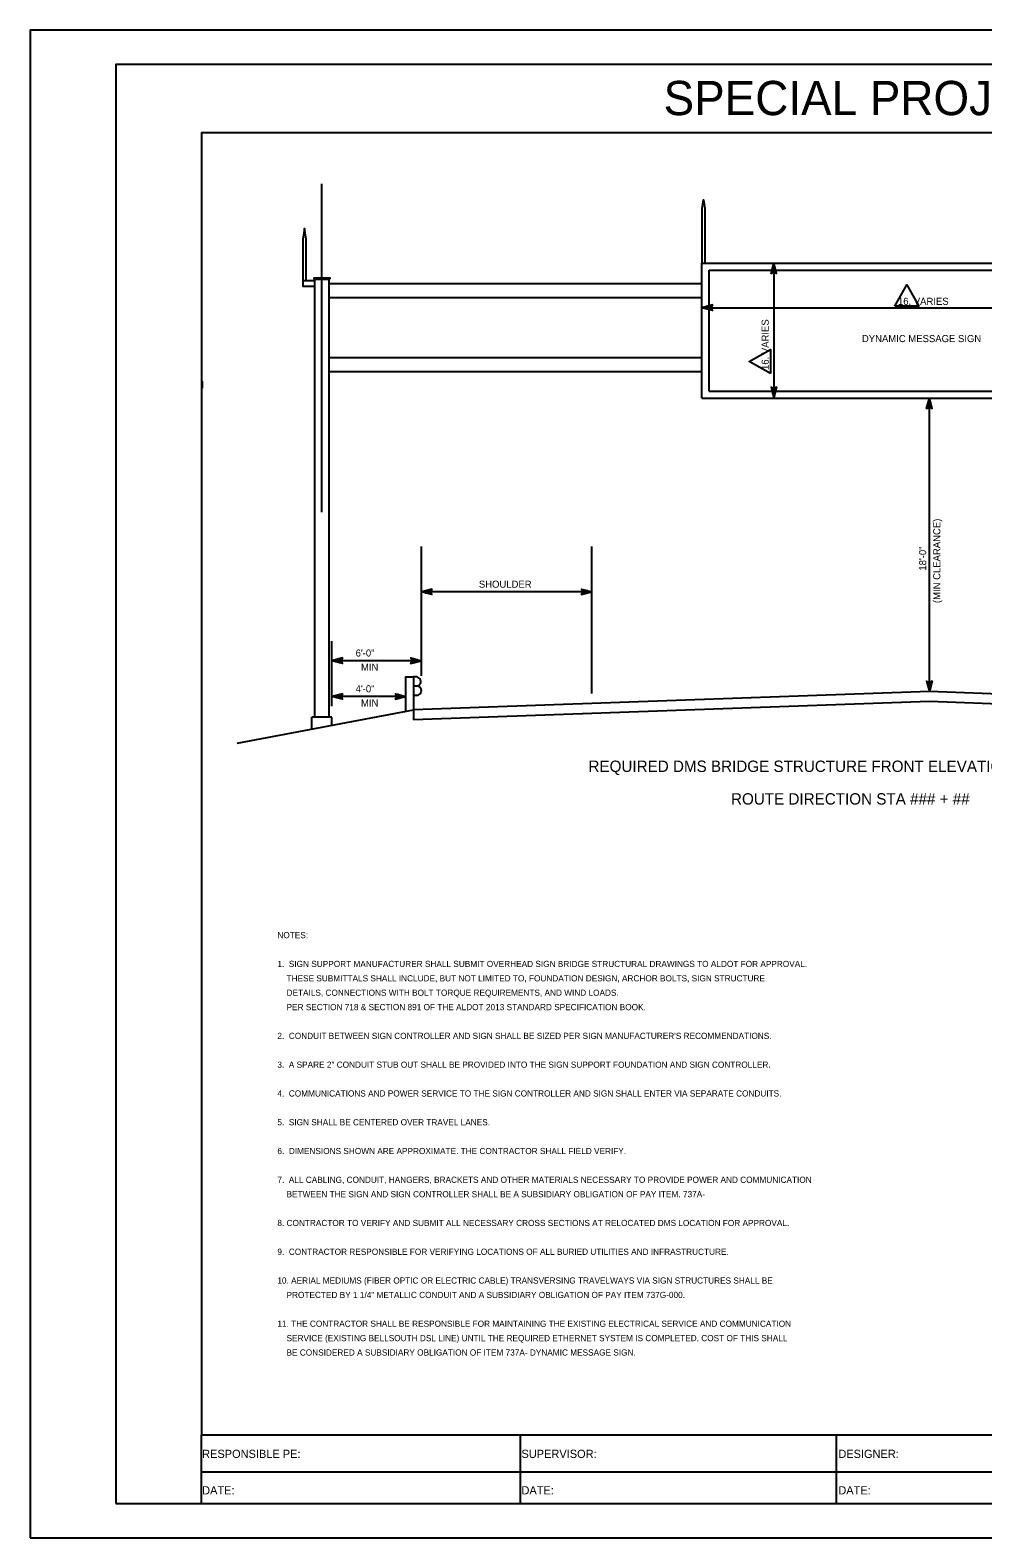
# Model space of a CAD drawing. Extents: x 515543 to 517243, y 661761 to 662861.
# Drawn here: x 515543 to 516238, y 661761 to 662861 of the extents above; entities that cross this region are included whole.
import ezdxf

# ---------------------------------------------------------------- set-up
doc = ezdxf.new("R2010")
doc.units = 0
for name, color, linetype in [('2', 7, 'Continuous'), ('ANNO-SHT', 7, 'Continuous'), ('ANNO-TXT', 7, 'Continuous'), ('AXIS', 7, 'Continuous'), ('Level 40', 7, 'Continuous'), ('Level 62', 7, 'Continuous'), ('Level 8', 7, 'Continuous'), ('LTT', 7, 'Continuous'), ('SHT-BDR', 7, 'Continuous'), ('SHT-BNDRY', 7, 'Continuous')]:
    doc.layers.add(name, color=color, linetype=linetype)

msp = doc.modelspace()

# ---------------------------------------------------------------- linework, layer by layer
at = {"layer": '2'}
msp.add_lwpolyline([(515668.1, 662604.6), (515668, 662599.6)], dxfattribs=at)
msp.add_lwpolyline([(515668.1, 662604.6), (515668, 662599.6)], dxfattribs=at)
at = {"layer": 'AXIS'}
msp.add_line((515667.5, 662385.7), (515667.5, 662385.8), dxfattribs=at)
at = {"layer": 'Level 40'}
for points in [[(516032.9, 662690.7), (516032.9, 662730.5), (516033.9, 662737), (516034.9, 662730.5), (516034.9, 662690.7)], [(515743.8, 662677.9), (515743.8, 662708.2), (515742.6, 662715.9), (515741.4, 662708.2), (515741.4, 662677.9)]]:
    msp.add_lwpolyline(points, dxfattribs=at)
msp.add_lwpolyline([(515750.2, 662677.9), (515741.4, 662677.9), (515741.4, 662674), (515750.2, 662674)], close=True, dxfattribs=at)
at = {"layer": 'Level 62'}
msp.add_lwpolyline([(515542.5, 661760.7), (517242.5, 661760.7), (517242.5, 662860.7), (515542.5, 662860.7)], close=True, dxfattribs=at)
at = {"layer": 'Level 8'}
for p, q in [((515755.4, 662509), (515755.4, 662748.7)), ((516032.7, 662592.2), (516032.7, 662690.7)), ((516037.9, 662597.4), (516037.9, 662685.6)), ((516085.1, 662690.7), (516085.1, 662592.2)), ((515749.7, 662679.1), (515761.1, 662679.1)), ((515750.2, 662359.5), (515750.2, 662679.1)), ((515760.6, 662359.5), (515760.6, 662679.1)), ((515760.6, 662676), (516032.7, 662676)), ((515760.6, 662665.6), (516032.7, 662665.6)), ((516032.7, 662658.2), (516369.7, 662658.2)), ((515760.6, 662622), (516032.7, 662622)), ((515760.6, 662611.6), (516032.7, 662611.6)), ((516037.9, 662597.4), (516364.5, 662597.4)), ((516032.7, 662592.2), (516369.7, 662592.2)), ((516198.6, 662378.1), (516198.6, 662592.2)), ((515828, 662389.6), (515828, 662484.1)), ((515952.4, 662376.7), (515952.4, 662484.1)), ((515952.4, 662450.9), (515828, 662450.9)), ((515828, 662400.7), (515762.7, 662400.7)), ((515824.1, 662388.9), (515822.3, 662389)), ((515824.4, 662382.1), (515822.3, 662382.1)), ((515816.6, 662374.6), (515762.7, 662374.6)), ((515824.8, 662375.4), (515822.3, 662375.4)), ((515748.1, 662350.8), (515748.1, 662359.5)), ((515762.7, 662359.5), (515748.1, 662359.5)), ((515762.7, 662353.6), (515762.7, 662359.5))]:
    msp.add_line(p, q, dxfattribs=at)
for points in [[(516032.7, 662690.7), (516369.7, 662690.7), (516369.7, 662592.2)], [(516037.9, 662685.6), (516364.5, 662685.6), (516364.5, 662597.4)], [(515749.7, 662679.1), (515749.7, 662680.1), (515761.1, 662680.1), (515761.1, 662679.1)], [(515816.6, 662363.7), (515816.6, 662389), (515822.3, 662389), (515822.3, 662364.8)]]:
    msp.add_lwpolyline(points, dxfattribs=at)
for centre in [(515824.2, 662385.5), (515824.6, 662378.8)]:
    msp.add_arc(centre, 3.38, 272.7797, 93.0419, dxfattribs=at)
at = {"layer": 'LTT'}
for points in [[(516083.1, 662683.1), (516085.1, 662690.7)], [(516085.1, 662684.5), (516084.4, 662687.9), (516084.4, 662684), (516083.8, 662685.3), (516083.8, 662684), (516083.1, 662683.1), (516085.1, 662684.3)], [(516087.1, 662683.1), (516085.1, 662690.7)], [(516085.1, 662684.5), (516085.8, 662687.9), (516085.8, 662684), (516086.4, 662685.3), (516086.4, 662684), (516087.1, 662683.1), (516085.1, 662684.3)], [(516040.4, 662660.2), (516032.7, 662658.2)], [(516040.4, 662656.3), (516032.7, 662658.2)], [(516039, 662658.2), (516035.6, 662658.9), (516039.5, 662658.9), (516038.2, 662659.5), (516039.5, 662659.5), (516040.4, 662660.2), (516039.2, 662658.2)], [(516039, 662658.2), (516035.6, 662657.6), (516039.5, 662657.6), (516038.2, 662656.9), (516039.5, 662656.9), (516040.4, 662656.3), (516039.2, 662658.2)], [(516085.1, 662599), (516084.4, 662595.5), (516084.4, 662599.4), (516083.8, 662598.2), (516083.8, 662599.5), (516083.1, 662600.3), (516085.1, 662599.1)], [(516083.1, 662600.3), (516085.1, 662592.7)], [(516085.1, 662599), (516085.8, 662595.5), (516085.8, 662599.4), (516086.4, 662598.2), (516086.4, 662599.5), (516087.1, 662600.3), (516085.1, 662599.1)], [(516087.1, 662600.3), (516085.1, 662592.7)], [(516196.6, 662584.6), (516198.6, 662592.2)], [(516198.6, 662586), (516197.9, 662589.4), (516197.9, 662585.5), (516197.3, 662586.8), (516197.3, 662585.5), (516196.6, 662584.6), (516198.6, 662585.8)], [(516200.6, 662584.6), (516198.6, 662592.2)], [(516198.6, 662586), (516199.3, 662589.4), (516199.3, 662585.5), (516199.9, 662586.8), (516199.9, 662585.5), (516200.6, 662584.6), (516198.6, 662585.8)], [(515835.6, 662452.9), (515828, 662450.9)], [(515835.6, 662448.9), (515828, 662450.9)], [(515834.3, 662450.9), (515830.8, 662451.6), (515834.7, 662451.6), (515833.4, 662452.2), (515834.8, 662452.2), (515835.6, 662452.9), (515834.4, 662450.9)], [(515834.3, 662450.9), (515830.8, 662450.2), (515834.7, 662450.2), (515833.4, 662449.6), (515834.8, 662449.6), (515835.6, 662448.9), (515834.4, 662450.9)], [(515946.1, 662450.9), (515949.5, 662451.6), (515945.7, 662451.6), (515946.9, 662452.2), (515945.6, 662452.2), (515944.7, 662452.9), (515946, 662450.9)], [(515944.7, 662452.9), (515952.4, 662450.9)], [(515946.1, 662450.9), (515949.5, 662450.2), (515945.7, 662450.2), (515946.9, 662449.6), (515945.6, 662449.6), (515944.7, 662448.9), (515946, 662450.9)], [(515944.7, 662448.9), (515952.4, 662450.9)], [(515770.3, 662402.7), (515762.7, 662400.7)], [(515770.3, 662398.7), (515762.7, 662400.7)], [(515768.9, 662400.7), (515765.5, 662401.4), (515769.4, 662401.4), (515768.1, 662402), (515769.4, 662402), (515770.3, 662402.7), (515769.1, 662400.7)], [(515768.9, 662400.7), (515765.5, 662400), (515769.4, 662400), (515768.1, 662399.4), (515769.4, 662399.4), (515770.3, 662398.7), (515769.1, 662400.7)], [(515821.7, 662400.7), (515825.1, 662401.4), (515821.3, 662401.4), (515822.5, 662402), (515821.2, 662402), (515820.3, 662402.7), (515821.6, 662400.7)], [(515820.3, 662402.7), (515828, 662400.7)], [(515821.7, 662400.7), (515825.1, 662400), (515821.3, 662400), (515822.5, 662399.4), (515821.2, 662399.4), (515820.3, 662398.7), (515821.6, 662400.7)], [(515820.3, 662398.7), (515828, 662400.7)], [(516198.6, 662384.4), (516197.9, 662381), (516197.9, 662384.9), (516197.3, 662383.6), (516197.3, 662384.9), (516196.6, 662385.8), (516198.6, 662384.5)], [(516196.6, 662385.8), (516198.6, 662378.1)], [(516198.6, 662384.4), (516199.3, 662381), (516199.3, 662384.9), (516199.9, 662383.6), (516199.9, 662384.9), (516200.6, 662385.8), (516198.6, 662384.5)], [(516200.6, 662385.8), (516198.6, 662378.1)], [(515770.3, 662376.6), (515762.7, 662374.6)], [(515770.3, 662372.6), (515762.7, 662374.6)], [(515768.9, 662374.6), (515765.5, 662375.3), (515769.4, 662375.3), (515768.1, 662375.9), (515769.4, 662375.9), (515770.3, 662376.6), (515769.1, 662374.6)], [(515768.9, 662374.6), (515765.5, 662373.9), (515769.4, 662373.9), (515768.1, 662373.3), (515769.4, 662373.3), (515770.3, 662372.6), (515769.1, 662374.6)], [(515810.4, 662374.6), (515813.8, 662375.3), (515809.9, 662375.3), (515811.2, 662375.9), (515809.9, 662375.9), (515809, 662376.6), (515810.2, 662374.6)], [(515809, 662376.6), (515816.6, 662374.6)], [(515810.4, 662374.6), (515813.8, 662373.9), (515809.9, 662373.9), (515811.2, 662373.3), (515809.9, 662373.3), (515809, 662372.6), (515810.2, 662374.6)], [(515809, 662372.6), (515816.6, 662374.6)]]:
    msp.add_lwpolyline(points, dxfattribs=at)
at = {"layer": 'SHT-BDR'}
msp.add_lwpolyline([(515667.5, 661835.8), (517167.5, 661835.8), (517167.5, 662785.8), (515667.5, 662785.8)], close=True, dxfattribs=at)
at = {"layer": 'SHT-BNDRY'}
for p, q in [((515762.7, 662367.5), (515762.7, 662415)), ((516198.6, 662378.1), (515822.3, 662364.8)), ((516580.1, 662364.8), (516198.6, 662378.1)), ((516198.6, 662370.8), (515822.3, 662357.5)), ((516580.1, 662357.5), (516198.6, 662370.8)), ((515693.6, 662340.6), (515822.3, 662364.8)), ((515822.3, 662364.8), (515822.3, 662357.5)), ((515667.5, 661785.7), (515667.5, 661835.8)), ((515900.1, 661835.8), (515900.1, 661785.7)), ((516130.8, 661785.7), (516130.8, 661835.8)), ((515667.5, 661808.8), (516445.6, 661808.8))]:
    msp.add_line(p, q, dxfattribs=at)
for points in [[(515605, 661785.7), (517217.5, 661785.7), (517217.5, 662835.7), (515605, 662835.7)], [(516173.3, 662659.3), (516182.2, 662674.8), (516190.9, 662659.3)], [(516082.6, 662610.1), (516067.2, 662619), (516082.6, 662627.7)]]:
    msp.add_lwpolyline(points, close=True, dxfattribs=at)

# ---------------------------------------------------------------- texts
at = {"layer": 'ANNO-SHT'}
msp.add_text('         SPECIAL PROJECT DETAIL         ', height=24.998, dxfattribs=at).set_placement((515921.1, 662798.7))
at = {"layer": 'ANNO-TXT'}
for s, p in [('RESPONSIBLE PE:', (515668, 661819)), ('SUPERVISOR:', (515901, 661819)), ('DESIGNER:', (516132.2, 661819)), ('DATE:', (515668, 661792.4)), ('DATE:', (515901, 661792.4)), ('DATE:', (516132.2, 661792.4))]:
    msp.add_text(s, height=6, rotation=360, dxfattribs=at).set_placement(p)
at = {"layer": 'Level 8'}
for s, height, rotation, p in [('16. VARIES', 5.18, 360, (516175.7, 662660.3)), ('16. VARIES', 5.18, 90, (516081.4, 662612.8)), ('DYNAMIC MESSAGE SIGN', 5.184, 360, (516149.4, 662633.1)), ('(MIN CLEARANCE)', 5.184, 90, (516206.6, 662442.7)), ('18\'-0"', 5.18, 90, (516196.3, 662466.4)), ('REQUIRED DMS BRIDGE STRUCTURE FRONT ELEVATION (N.T.S)', 8.294, 360, (515949.9, 662319.5)), ('ROUTE DIRECTION STA ### + ##', 8.294, 360, (516053.9, 662295.7)), ('NOTES:', 4.5, 360, (515722.9, 662198.2)), ('1.  SIGN SUPPORT MANUFACTURER SHALL SUBMIT OVERHEAD SIGN BRIDGE STRUCTURAL DRAWINGS TO ALDOT FOR APPROVAL.', 4.5, 360, (515722.9, 662177.2)), ('    THESE SUBMITTALS SHALL INCLUDE, BUT NOT LIMITED TO, FOUNDATION DESIGN, ARCHOR BOLTS, SIGN STRUCTURE', 4.5, 360, (515722.9, 662166.7)), ('    DETAILS, CONNECTIONS WITH BOLT TORQUE REQUIREMENTS, AND WIND LOADS.', 4.5, 360, (515722.9, 662156.2)), ('    PER SECTION 718 & SECTION 891 OF THE ALDOT 2013 STANDARD SPECIFICATION BOOK.', 4.5, 360, (515722.9, 662145.7)), ("2.  CONDUIT BETWEEN SIGN CONTROLLER AND SIGN SHALL BE SIZED PER SIGN MANUFACTURER'S RECOMMENDATIONS.", 4.5, 360, (515722.9, 662124.7)), ('3.  A SPARE 2" CONDUIT STUB OUT SHALL BE PROVIDED INTO THE SIGN SUPPORT FOUNDATION AND SIGN CONTROLLER.', 4.5, 360, (515722.9, 662103.7)), ('4.  COMMUNICATIONS AND POWER SERVICE TO THE SIGN CONTROLLER AND SIGN SHALL ENTER VIA SEPARATE CONDUITS.', 4.5, 360, (515722.9, 662082.7)), ('5.  SIGN SHALL BE CENTERED OVER TRAVEL LANES.', 4.5, 360, (515722.9, 662061.7)), ('6.  DIMENSIONS SHOWN ARE APPROXIMATE. THE CONTRACTOR SHALL FIELD VERIFY.', 4.5, 360, (515722.9, 662040.7)), ('7.  ALL CABLING, CONDUIT, HANGERS, BRACKETS AND OTHER MATERIALS NECESSARY TO PROVIDE POWER AND COMMUNICATION', 4.5, 360, (515722.9, 662019.7)), ('    BETWEEN THE SIGN AND SIGN CONTROLLER SHALL BE A SUBSIDIARY OBLIGATION OF PAY ITEM. 737A-', 4.5, 360, (515722.9, 662009.2)), ('8. CONTRACTOR TO VERIFY AND SUBMIT ALL NECESSARY CROSS SECTIONS AT RELOCATED DMS LOCATION FOR APPROVAL.', 4.5, 360, (515722.9, 661988.2)), ('9.  CONTRACTOR RESPONSIBLE FOR VERIFYING LOCATIONS OF ALL BURIED UTILITIES AND INFRASTRUCTURE.', 4.5, 360, (515722.9, 661967.2)), ('10. AERIAL MEDIUMS (FIBER OPTIC OR ELECTRIC CABLE) TRANSVERSING TRAVELWAYS VIA SIGN STRUCTURES SHALL BE', 4.5, 360, (515722.9, 661946.2)), ('    PROTECTED BY 1 1/4" METALLIC CONDUIT AND A SUBSIDIARY OBLIGATION OF PAY ITEM 737G-000.', 4.5, 360, (515722.9, 661935.7)), ('11. THE CONTRACTOR SHALL BE RESPONSIBLE FOR MAINTAINING THE EXISTING ELECTRICAL SERVICE AND COMMUNICATION', 4.5, 360, (515722.9, 661914.7)), ('    SERVICE (EXISTING BELLSOUTH DSL LINE) UNTIL THE REQUIRED ETHERNET SYSTEM IS COMPLETED. COST OF THIS SHALL', 4.5, 360, (515722.9, 661904.2)), ('    BE CONSIDERED A SUBSIDIARY OBLIGATION OF ITEM 737A- DYNAMIC MESSAGE SIGN.', 4.5, 360, (515722.9, 661893.7))]:
    msp.add_text(s, height=height, rotation=rotation, dxfattribs=at).set_placement(p)
for s, p in [('SHOULDER', (515869.9, 662453.9)), ('6\'-0"', (515780, 662403.7)), ('MIN', (515783.9, 662393.3)), ('4\'-0"', (515780, 662377.6)), ('MIN', (515783.9, 662367.2))]:
    msp.add_text(s, height=5.18, dxfattribs=at).set_placement(p)

doc.saveas('drawing.dxf')
